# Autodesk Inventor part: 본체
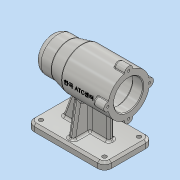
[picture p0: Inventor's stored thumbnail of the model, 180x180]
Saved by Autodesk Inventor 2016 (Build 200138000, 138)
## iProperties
Created: 2019-07
Part Number: 본체
Material: 알루미늄 6061
Document SubType Name: Modeling
Designer: MIRAE
Density: 2.7 g/cm^3
Appearance: 알루미늄 - 평지
Mass: 644.605 g
Surface Area: 653.565 cm^2
Volume: 238.743 cm^3
Author: MIRAE
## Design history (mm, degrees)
sketch "스케치1"
  geometry: L1 (0, 0)-(112, 0); L2 (112, 0)-(112, -70); L3 (112, -70)-(0, -70); L4 (0, -70)-(0, 0)
  constraints: 8 end point, 2 parallel, 1 horizontal, 1 perpendicular
  dimensions: "d0" = 112 distance of L2.end L3.end; "d1" = 70 distance of L1.end L2.end
extrude "돌출1" new body sketch "스케치1" distance "d2" = 10; taper "d3" = 0 deg
node "작업 평면1"
sketch "스케치17"
  geometry: L1 (-112, 0)-(0, 0) reference; L2 (-112, 0)-(-112, 10) reference; L3 (0, 10)-(-112, 10) reference; L4 (0, 0)-(0, 10) reference; L5 (0, 80)-(-112, 80); L6 (0, 80)-(0, 110); L7 (0, 110)-(-67, 110); L8 (-67, 110)-(-87, 105); L9 (-87, 105)-(-112, 105); L10 (-112, 105)-(-112, 80); L11 (0, 101)-(-15, 101); L12 (-15, 101)-(-15, 104); L13 (-15, 104)-(-69, 104); L14 (-69, 104)-(-69, 101); L15 (-69, 101)-(-81, 101); L16 (-81, 101)-(-81, 97.5); L17 (-81, 97.5)-(-99, 97.5); L18 (-99, 97.5)-(-99, 96); L19 (-103, 96)-(-99, 96); L20 (-103, 96)-(-103, 90.5); L21 (-103, 90.5)-(-106, 90.5); L22 (-106, 90.5)-(-106, 80); 1 further point
  constraints: 36 end point, 10 perpendicular, 4 point on line, 3 horizontal, 2 vertical, 1 parallel, 1 vertical alignment
  dimensions: "d103" = 80 distance from line of L1 L5.end; "d104" = 60 diameter of L7 L5; "d105" = 50 diameter of L9 L5; "d106" = 112 distance of L5.start L5.end; "d107" = 45 distance from line of L10 L7.end; "d108" = 25 distance from line of L10 L8.end; "d109" = 42 diameter of L11 L5; "d110" = 48 diameter of L13 L5; "d111" = 35 diameter of L17 L5; "d112" = 32 diameter of L19 L5; "d113" = 21 diameter of L21 L5; "d114" = 15 distance of L11.start L11.end; "d115" = 12 distance of L14.end L15.end; "d116" = 3 distance of L20.end L21.end; "d117" = 4 distance of L19.start L18.end; "d118" = 18 distance of L16.end L17.end; "d119" = 54 distance of L12.end L13.end
revolve "회전2" sketch "스케치17" stored, may be unused: angle "d120" = 90 deg
node "작업 평면5"
sketch "스케치18"
  geometry: L1 (-36.815, 10.272)-(19.815, 10.272); L2 (19.815, 10.272)-(19.815, -10.272); L3 (19.815, -10.272)-(-36.815, -10.272); L4 (-36.815, -10.272)-(-36.815, 10.272); L5 (-33.5, -30)-(-33.5, 30) reference; L6 (33.5, -30)-(33.5, 30) reference; L7 (-8.5, 10.272)-(-8.5, 15.234); 3 further points
  constraints: 3 midpoint, 2 end point, 1 horizontal alignment, 1 vertical, 2 other
  dimensions: "d121" = 42 distance between parallel lines of L6 L7
feature "엠보싱2" sketch "스케치18" dims "d0" = 112, "d1" = 70, "d103" = 80, "d104" = 60, "d105" = 50, "d106" = 112, "d107" = 45, "d108" = 25, "d109" = 42, "d110" = 48, "d111" = 35, "d112" = 32, "d113" = 21, "d114" = 15, "d115" = 12, "d116" = 3, "d117" = 4, "d118" = 18, "d119" = 54, "d122" = 0.5, "d123" = 0
sketch "스케치19"
  geometry: L1 (0, 0)-(112, 0) reference; L2 (112, 0)-(112, -70) reference; L3 (112, -70)-(0, -70) reference; L4 (0, -70)-(0, 0) reference; L5 (56, -39)-(25, -39); L6 (25, -39)-(25, -31); L7 (25, -31)-(56, -31); L8 (56, -31)-(56, -39); 3 further points
  constraints: 8 end point, 2 midpoint, 2 parallel, 1 horizontal, 1 horizontal alignment, 1 perpendicular
  dimensions: "d124" = 8 distance of L5.end L6.end; "d125" = 25 distance between parallel lines of L4 L6; "d126" = 56 distance between parallel lines of L4 L8
extrude "돌출5" join sketch "스케치19" stored distance "d127" = 16; taper "d128" = 0 deg
sketch "스케치20"
  geometry: L1 (-87, 55)-(-67, 50) reference; L2 (-67, 50)-(0, 50) reference; L3 (-56, 10)-(-56, 50.268) reference; L4 (-112, 0)-(0, 0) reference; L5 (-112, 0)-(-112, 10) reference; L6 (0, 10)-(-112, 10) reference; L7 (0, 0)-(0, 10) reference; L8 (-92, 10)-(-76.57, 52.393); 1 further point
  constraints: 2 end point, 2 point on line
  dimensions: "d129" = 110 deg angle of L6 L8; "d130" = 20 distance from line of L8.start L5
feature "리브3" sketch "스케치20" dims "d131" = 1, "d132" = 8, "d133" = 0, "d134" = 0, "d135" = 1, "d136" = 1
node "작업 평면6"
sketch "스케치21"
  geometry: L1 (0, 0)-(-70, 0) reference; L2 (0, 0)-(0, 10) reference; L3 (-70, 10)-(0, 10) reference; L4 (-70, 0)-(-70, 10) reference; L5 (-39, 52.659)-(-39, 10) reference; L6 (-31, 10)-(-39, 10) reference; L7 (-31, 10)-(-31, 52.659) reference; L8 (-39, 50.268)-(-39, 52.659) reference; L9 (-31, 52.659)-(-31, 50.268) reference; L10 (-7, 10)-(-15.346, 57.334); C1 r 25 at (-35, 80) reference; A1 r 30 centre (-35, 80) between (-31, 50.268) and (-39, 50.268) reference; 3 further points; 2 other entities
  constraints: 2 end point, 1 point on circle, 1 point on line, 2 other
  dimensions: "d138" = 100 deg angle of L3 L10; "d139" = 7 distance from line of L10.start L2
feature "리브4" sketch "스케치21" dims "d140" = 1, "d141" = 8, "d142" = 0, "d143" = 0, "d144" = 1, "d145" = 1
fillet "모깎기13" dims "d146" = 10
chamfer "모따기3" distance "d147" = 3; stored, may be unused: second distance "d148" = 2, angle "d149" = 45 deg
sketch "스케치22"
  geometry: C1 r 21 at (0, 0) reference; C2 r 6 at (30, 0); 2 further points
  constraints: 2 horizontal alignment, 1 centre point, 1 other
  dimensions: "d150" = 12 diameter of C2
extrude "돌출6" join sketch "스케치22" distance "d151" = 16; taper "d152" = 0 deg
sketch "스케치23"
  geometry: C1 r 21 at (-30, 0) reference; A1 r 30 centre (-30, 0) between (-0.6, 5.97) and (-0.6, -5.97) reference; A2 r 6 centre (0, 0) between (-0.6, -5.97) and (-0.6, 5.97) reference; 2 further points
  constraints: 1 coincident
hole "구멍2" sketch "스케치23" at (0, 0) diameter "d153" = 3.242; stored, may be unused: countersink angle "d157" = 90 deg, drill point angle "d159" = 118 deg; dims "d154" = 8, "d155" = 4, "d156" = 2, "d158" = 11
fillet "모깎기14" dims "d160" = 3
fillet "모깎기15" dims "d161" = 1
sketch "스케치24"
  geometry: L1 (102, -70)-(10, -70) reference; L2 (0, -60)-(0, -10) reference; L3 (10, 0)-(102, 0) reference; L4 (112, -10)-(112, -60) reference; C1 r 3 at (102, -10); C2 r 3 at (102, -60); C3 r 3 at (10, -60); C4 r 3 at (10, -10); A1 r 10 centre (102, -60) between (102, -70) and (112, -60) reference; A2 r 10 centre (10, -60) between (0, -60) and (10, -70) reference; A3 r 10 centre (10, -10) between (10, 0) and (0, -10) reference; A4 r 10 centre (102, -10) between (112, -10) and (102, 0) reference; 1 further point
  constraints: 4 centre point, 4 coincident
  dimensions: "d165" = 6 diameter of C1; "d166" = 6 diameter of C2; "d167" = 6 diameter of C3; "d168" = 6 diameter of C4
extrude "돌출7" cut sketch "스케치24" distance "d169" = 16; taper "d170" = 0 deg
fillet "모깎기16" dims "d171" = 3
fillet "모깎기17" dims "d172" = 3
fillet "모깎기18" dims "d173" = 3
fillet "모깎기19" dims "d174" = 3
fillet "모깎기20" dims "d175" = 3
fillet "모깎기21" dims "d176" = 0.3
fillet "모깎기22" dims "d177" = 3
chamfer "모따기4" distance "d178" = 1; stored, may be unused: second distance "d179" = 2, angle "d180" = 45 deg
node "솔리드1"
mirror "대칭4"
pattern_circular "원형 패턴2" dims "d163" = 360 deg
node "투영된 루프18"
node "투영된 루프19"
node "투영된 루프20"
node "투영된 루프21"
node "투영된 루프22"
node "투영된 루프23"
node "투영된 루프24"
node "투영된 루프25"
node "투영된 루프26"
node "투영된 루프27"
other parameters: "d4" = -35, "d137" = 56
